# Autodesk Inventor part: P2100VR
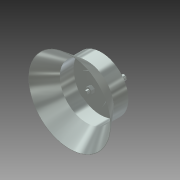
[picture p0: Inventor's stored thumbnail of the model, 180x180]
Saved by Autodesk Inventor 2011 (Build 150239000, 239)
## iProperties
Created: 2014-07
Part Number: P2100VR
Document SubType Name: Modeling
Designer: Evgeny
Density: 1 g/cm^3
Author: Evgeny
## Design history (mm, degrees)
sketch "Эскиз1"
  geometry: L1 (28, 24.187)-(28, -24.187); L2 (-28, -24.187)-(-28, 24.187); C1 r 1.35 at (13.5, -24); A1 r 37 centre (0, 0) between (28, 24.187) and (-28, 24.187); A2 r 37 centre (0, 0) between (-28, -24.187) and (28, -24.187); 1 further point
  constraints: 4 end point, 4 point on circle, 3 centre point, 1 coincident, 1 parallel
  dimensions: "d1" = 56 distance between parallel lines of L1 L2; "d2" = 28 distance from line of L2 point (0, 0); "d3" = 37 radius of A1; "d4" = 37 radius of A2; "d7" = 2.7 diameter of C1; "d9" = 24 vertical distance of point (0, 0) C1.centre; "d50" = 13.5 horizontal distance of C1.centre point (0, 0)
extrude "Выдавливание1" new body sketch "Эскиз1" distance "d10" = 1; taper "d11" = 0 deg
sketch "Эскиз2"
  geometry: C1 r 4 at (0, 0); A1 r 37 centre (0, 0) between (28, 24.187) and (-28, 24.187) reference
  constraints: 1 centre point, 1 coincident
  dimensions: "d12" = 8 diameter of C1
extrude "Выдавливание2" join sketch "Эскиз2" distance "d13" = 6; taper "d14" = 0 deg
sketch "Эскиз3"
  geometry: C1 r 4 at (0, 0) reference; C2 r 25 at (0, 0)
  constraints: 1 centre point, 1 coincident
  dimensions: "d15" = 50 diameter of C2
extrude "Выдавливание3" join sketch "Эскиз3" distance "d16" = 1; taper "d17" = 0 deg
sketch "Эскиз4"
  geometry: L1 (5.774, 0)-(2.887, -5); L2 (2.887, -5)-(-2.887, -5); L3 (-2.887, -5)-(-5.774, 0); L4 (-5.774, 0)-(-2.887, 5); L5 (-2.887, 5)-(2.887, 5); L6 (2.887, 5)-(5.774, 0); C1 r 25 at (0, 0) reference; 1 further point
  constraints: 12 end point, 1 coincident, 13 other
  dimensions: "d18" = 10 distance between parallel lines of L2 L5
extrude "Выдавливание4" join sketch "Эскиз4" distance "d19" = 6; taper "d20" = 0 deg
sketch "Эскиз5"
  geometry: C1 r 4 at (0, 0); A1 r 37 centre (0, 0) between (28, 24.187) and (-28, 24.187) reference
  constraints: 1 centre point, 1 coincident
  dimensions: "d21" = 8 diameter of C1
extrude "Выдавливание5" join sketch "Эскиз5" distance "d22" = 7; taper "d23" = 0 deg
sketch "Эскиз6"
  geometry: C1 r 4 at (0, 0) reference; C2 r 47.5 at (0, 0); C3 r 4 at (-13.5, -24)
  constraints: 2 centre point, 1 coincident
  dimensions: "d24" = 95 diameter of C2; "d33" = 8 diameter of C3; "d52" = 24 vertical distance of C1.centre C3.centre; "d53" = 13.5 horizontal distance of C1.centre C3.centre
extrude "Выдавливание11" join sketch "Эскиз6" distance "d38" = 1.5; taper "d39" = 0 deg
extrude "Выдавливание14" join sketch "Эскиз1" distance "d46" = 2; taper "d48" = 0 deg; dims "d47" = 24.5, "d49" = 0
sketch "Эскиз12"
  geometry: L1 (-47, 17.178)-(-71.354, 47); L2 (-71.354, 47)-(-72, 47); L3 (-72, 47)-(-47.5, 17); L4 (0, -19.6)-(0, 58.1) reference; L5 (-47, 17)-(-47, -8.5); L6 (-47, -8.5)-(-47.5, -8.5); L7 (-47.5, -8.5)-(-47.5, 17); L8 (-47, 17)-(-47, 17.178); 1 further point
  constraints: 14 end point, 3 parallel, 1 horizontal
  dimensions: "d65" = 0.5 distance between parallel lines of L5 L7; "d66" = 17 vertical distance of L3.end point (0, 0); "d67" = 25.5 distance from line of L6 L3.end; "d68" = 47.5 distance from line of point (0, 0) L7; "d69" = 30 distance from line of L2 L3.end; "d71" = 0.5 distance between parallel lines of L3 L1; "d83" = 72 distance from line of L2.end L4
revolve "Вращение1" sketch "Эскиз12" stored, may be unused: angle "d64" = 90 deg
sketch "Эскиз13"
  geometry: C1 r 4 at (-13.5, -24) reference; C2 r 4.5 at (-13.5, -24)
  constraints: 1 centre point, 1 coincident
  dimensions: "d73" = 9 diameter of C2
extrude "Выдавливание16" join sketch "Эскиз13" distance "d74" = 16; taper "d75" = 0 deg
sketch "Эскиз14"
  geometry: C1 r 47.5 at (0, 0) reference; C2 r 5 at (0, 0)
  constraints: 1 centre point, 1 coincident
  dimensions: "d76" = 10 diameter of C2
extrude "Выдавливание17" join sketch "Эскиз14" distance "d77" = 4; taper "d78" = 0 deg
fillet "Сопряжение1" dims "d79" = 4
sketch "Эскиз15"
  geometry: C1 r 3 at (0, 0); 1 further point
  constraints: 1 centre point, 1 coincident
  dimensions: "d80" = 6 diameter of C1
extrude "Выдавливание18" join sketch "Эскиз15" distance "d81" = 5; taper "d82" = 0 deg
node "Твердое тело1"
other parameters: "d0" = 82
